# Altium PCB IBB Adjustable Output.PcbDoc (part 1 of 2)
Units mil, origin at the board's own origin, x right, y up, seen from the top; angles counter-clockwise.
Board outline 3000 x 2700 mil, 4 copper layers (Top Layer, Signal Layer 1, Signal Layer 2, Bottom Layer), stack 61.2 mil thick; 75 components, 28 nets, 136 pads, 154 vias.
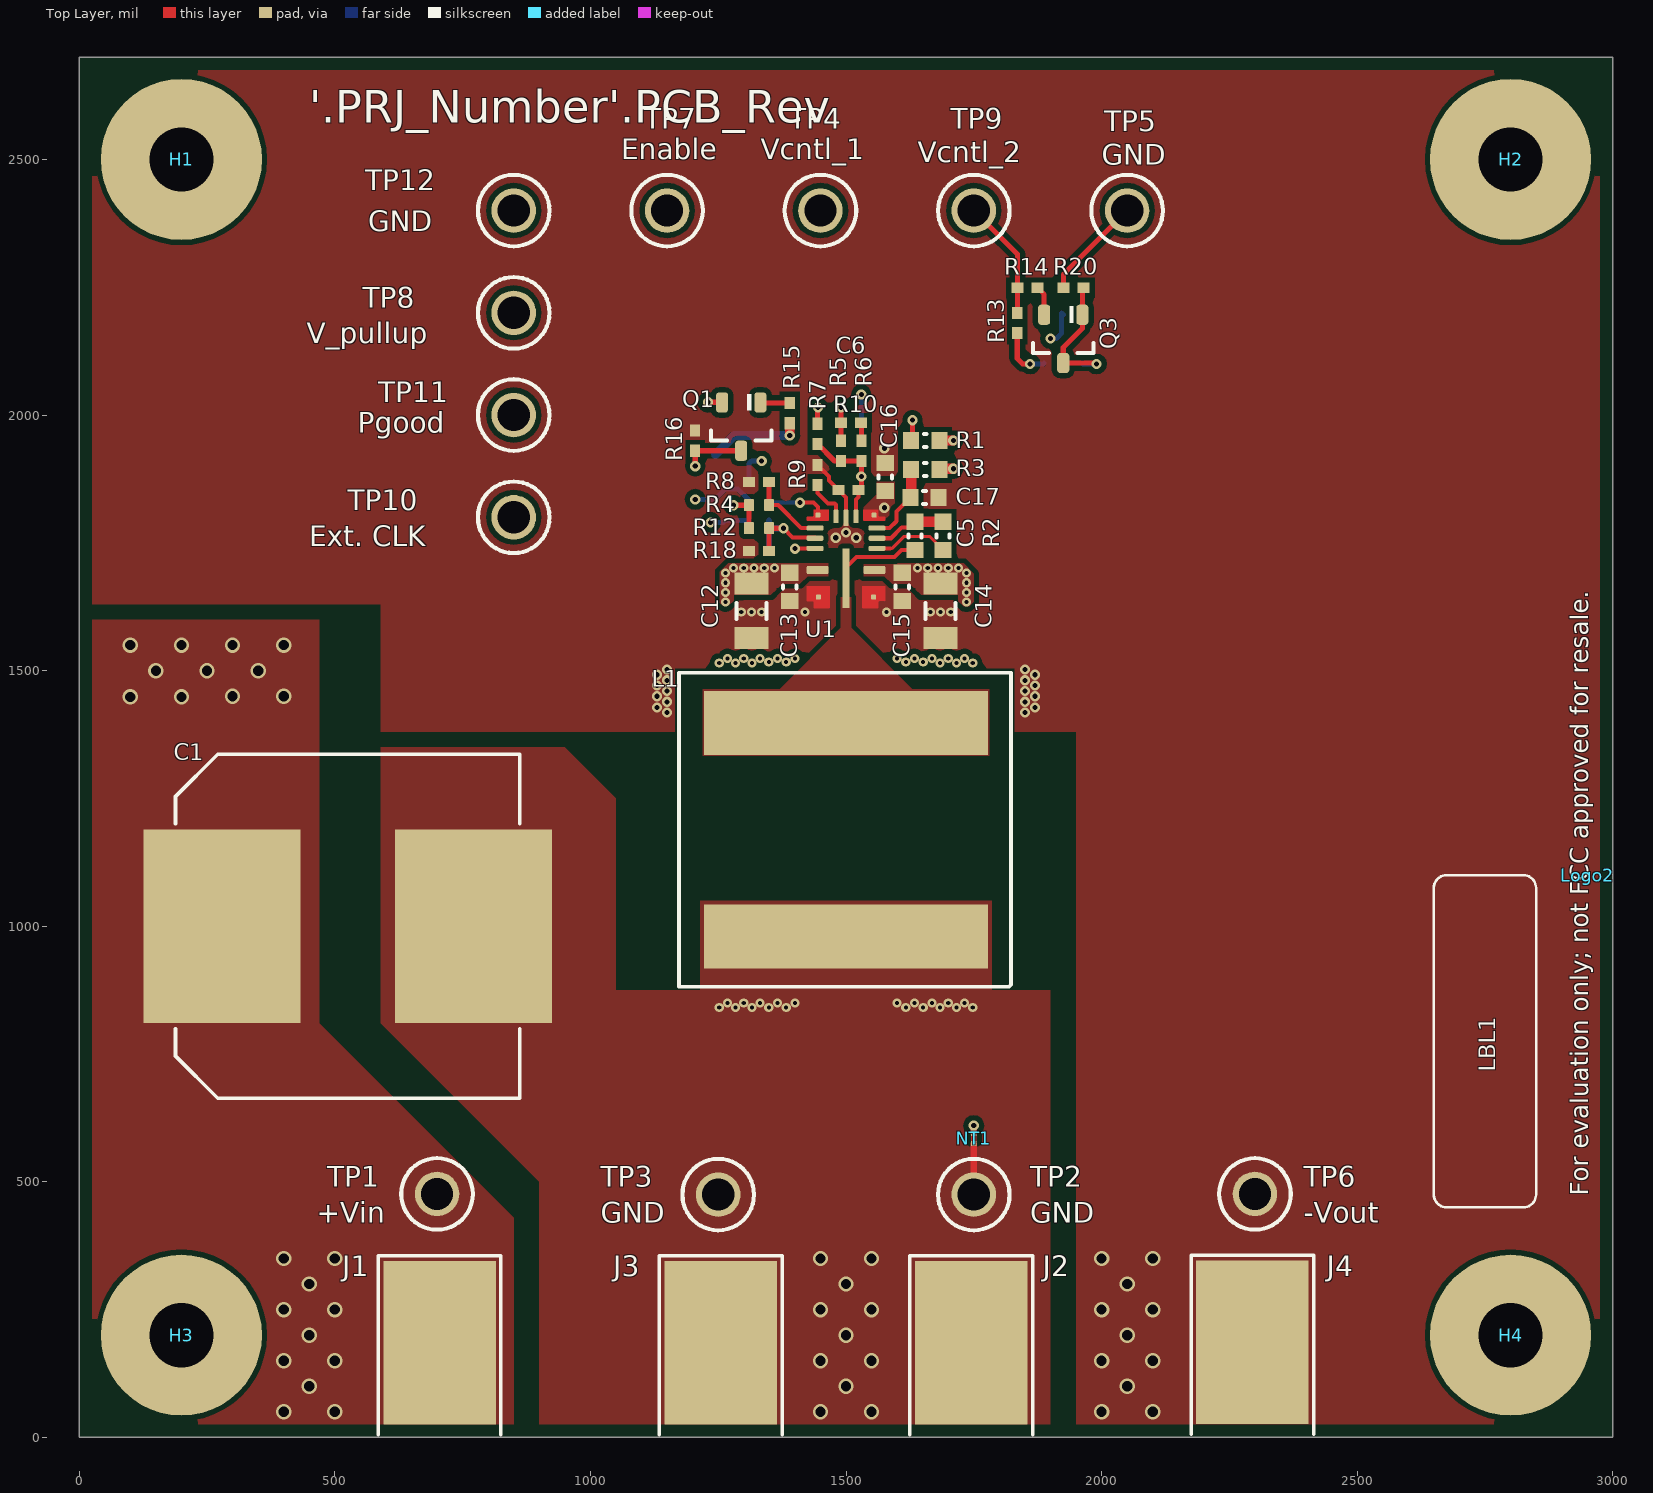
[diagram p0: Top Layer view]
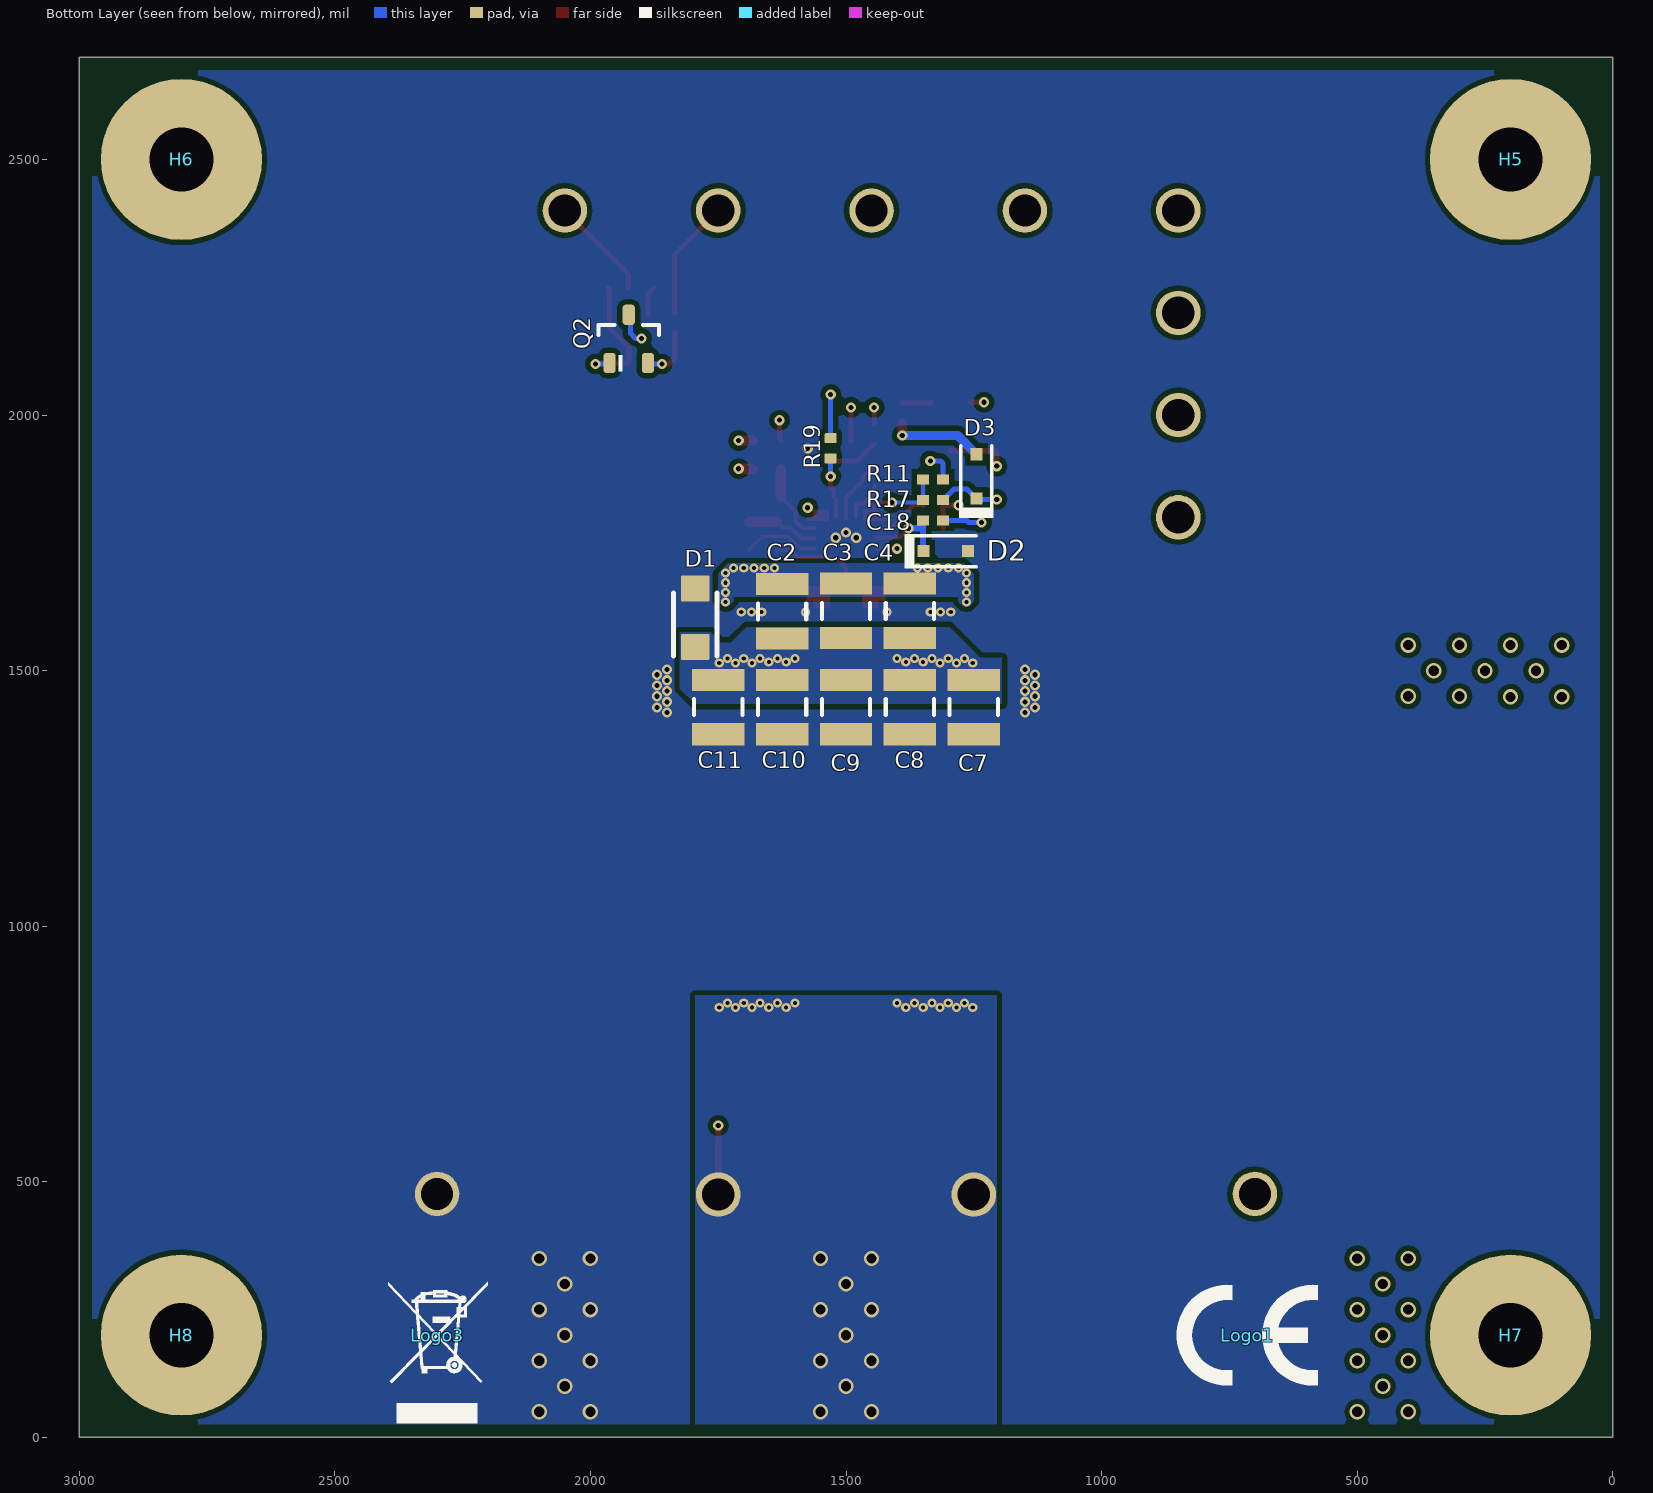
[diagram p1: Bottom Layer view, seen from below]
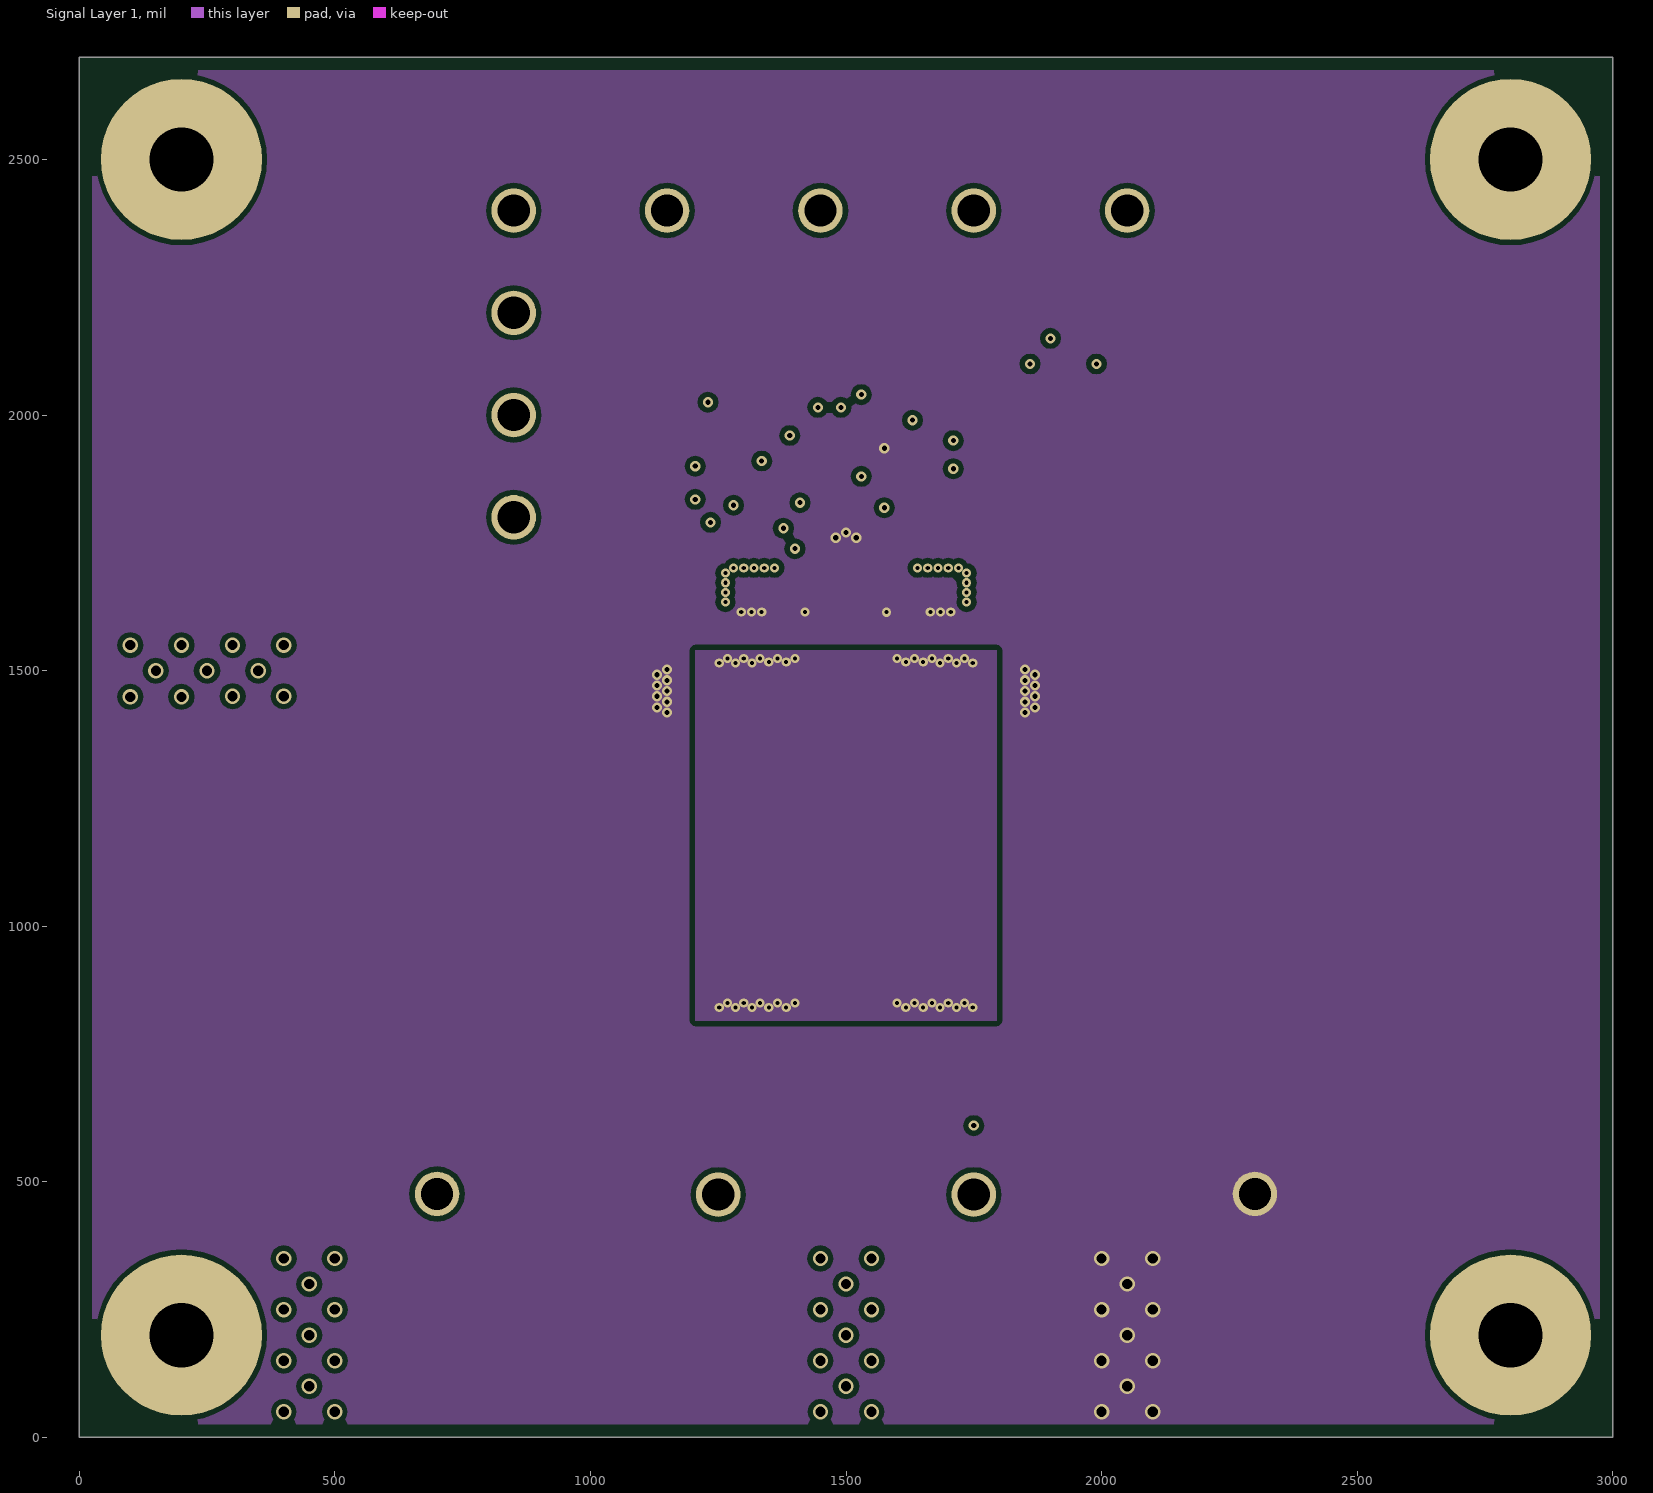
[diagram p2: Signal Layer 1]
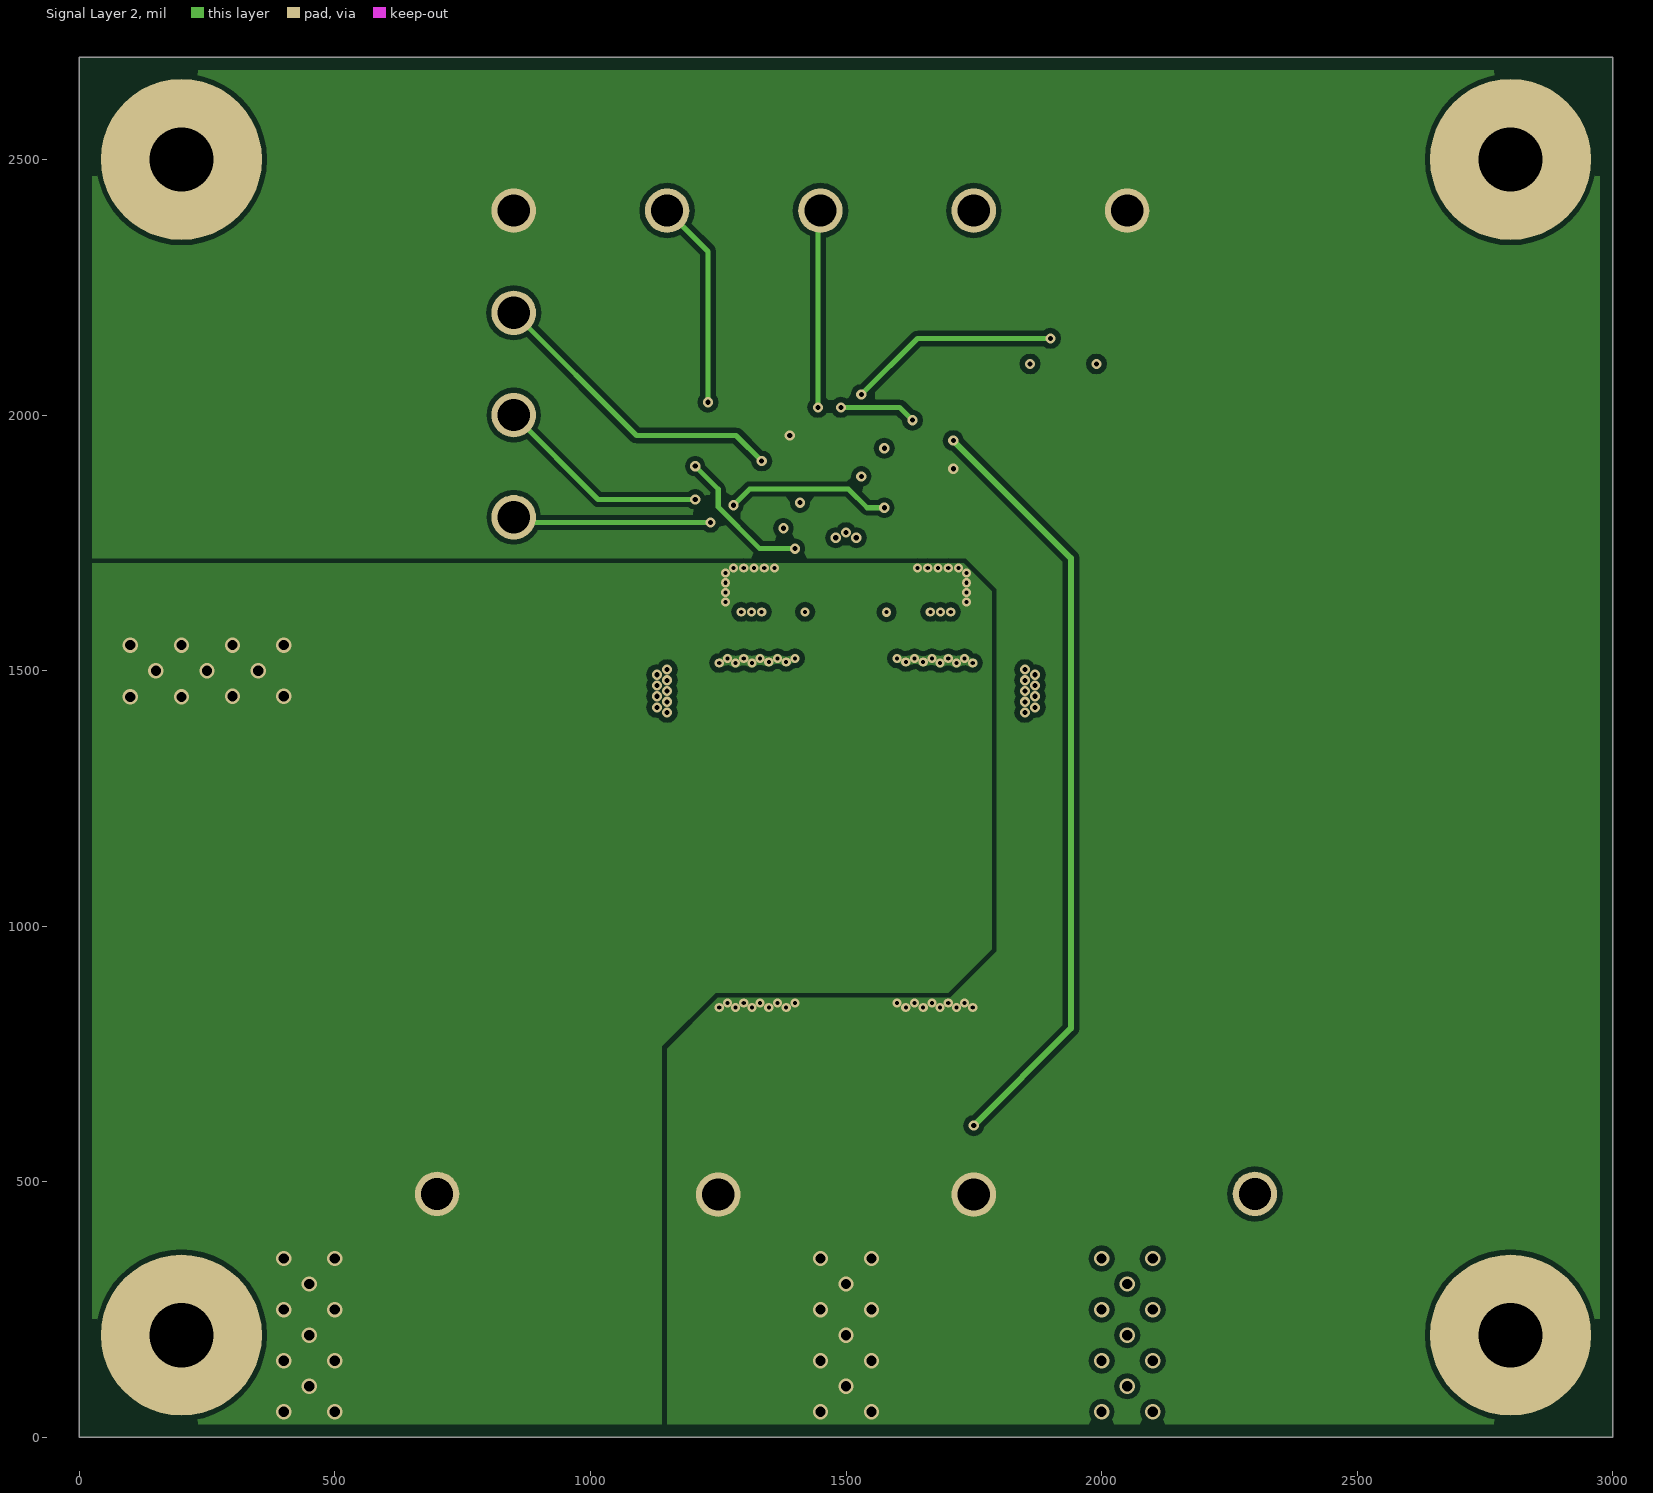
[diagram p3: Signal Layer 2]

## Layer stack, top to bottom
Top Solder: solder mask 0.4, Solder Resist, Dk 3.5
Top Layer: signal copper 1.4
Dielectric 2: prepreg 12.3, Dk 4.2
Signal Layer 1: signal copper 1.4
Dielectric 3: core 31, Dk 4.2
Signal Layer 2: signal copper 1.4
Dielectric1: prepreg 12.3, FR-4 High Tg, Dk 4.2
Bottom Layer: signal copper 1.4
Bottom Solder: solder mask 0.4, Solder Resist, Dk 3.5

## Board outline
0,0 3000,0 3000,2700 0,2700

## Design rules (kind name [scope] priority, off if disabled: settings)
AcuteAngle [All] p1: minimum=4.50000000000000E+0001 checktracksonly=FALSE
AssemblyTestPointUsage [All] p1: valid=2
BoardOutlineClearance BoardOutlineClearance_MountingHoles [OnCopper and InComponentClass('Mounting Holes')] p1: gap=40 ignorepadtopadclearanceinfootprint=FALSE
BoardOutlineClearance BoardOutlineClearance_Poly [OnCopper and IsPoly] p2: gap=25 ignorepadtopadclearanceinfootprint=FALSE
BoardOutlineClearance [OnCopper and Not InComponentClass('Logo') and not InComponentClass('FiducialMark') and not InRegion(1000,500,4000,800) and not InPoly] p3: gap=25 ignorepadtopadclearanceinfootprint=FALSE
Clearance Clearance_Keepouts [((IsTrack Or IsArc) And Not InPoly) And IsFree and IsKeepOut vs ((IsTrack Or IsArc) And Not InPoly) And IsFree and IsKeepOut] p1: gap=0 ignorepadtopadclearanceinfootprint=FALSE
Clearance Clearance_Poly [InPolygon] p2: gap=10 ignorepadtopadclearanceinfootprint=TRUE
Clearance Clearance_FiducialMark [IsKeepOut and InComponentClass('FiducialMark') vs IsPad and InComponentClass('FiducialMark')] p3: gap=0 ignorepadtopadclearanceinfootprint=FALSE
Clearance [All] p4: gap=7.87 ignorepadtopadclearanceinfootprint=TRUE
ComponentClearance ComponentClearance_MountingHoles_FiducialMarks [InComponentClass('Mounting Holes') vs InComponentClass('FiducialMark')] p1: gap=50 collisioncheckmode=3 verticalgap=10 showdistances=FALSE
ComponentClearance ComponentClearance_Shunt [InComponentClass('Header') vs InComponentClass('Shunt')] p2: gap=0 collisioncheckmode=3 verticalgap=0 showdistances=FALSE
ComponentClearance ComponentClearance_Logo [InComponentClass('Logo')] p3: gap=30 collisioncheckmode=3 verticalgap=10 showdistances=FALSE
ComponentClearance ComponentClearance_ScrewToNut [(HasFootprint('NY PMS 440 0025 PH')) vs (HasFootprint('Keystone_1902C'))] p4: gap=5 collisioncheckmode=3 verticalgap=10 showdistances=FALSE
ComponentClearance ComponentClearance_MountingHoles [InComponentClass('Mounting Holes')] p5: gap=100 collisioncheckmode=3 verticalgap=100000 showdistances=FALSE
ComponentClearance ComponentClearance_SmallPassives [HasFootprint('0201*') or HasFootprint('0402*') or HasFootprint('0508') or HasFootprint('0603*') or HasFootprint('0612') or HasFootprint('0805*') or HasFootprint('0815*') or HasFootprint('0830*') or HasFootprint('1206*') or HasFootprint('1210*') or HasFootprint('1808*') or HasFootprint('1812*') or HasFootprint('1825*') or HasFootprint('2010*') or HasFootprint('2220*') or HasFootprint('2225*') or HasFootprint('2512*') or HasFootprint('2728*') or HasFootprint('3518*') vs HasFootprint('0201*') or HasFootprint('0402*') or HasFootprint('0508') or HasFootprint('0603*') or HasFootprint('0612') or HasFootprint('0805*') or HasFootprint('0815*') or HasFootprint('0830*') or HasFootprint('1206*') or HasFootprint('1210*') or HasFootprint('1808*') or HasFootprint('1812*') or HasFootprint('1825*') or HasFootprint('2010*') or HasFootprint('2220*') or HasFootprint('2225*') or HasFootprint('2512*') or HasFootprint('2728*') or HasFootprint('3518*')] p6: gap=14.96 collisioncheckmode=3 verticalgap=10 showdistances=FALSE
ComponentClearance ComponentClearance_THtoSMT [IsThruComponent vs IsSMTComponent] p7: gap=30 collisioncheckmode=3 verticalgap=30 showdistances=FALSE
ComponentClearance ComponentClearance_THtoTH [IsThruComponent vs IsThruComponent] p8: gap=20 collisioncheckmode=3 verticalgap=30 showdistances=FALSE
ComponentClearance [All] p9: gap=20 collisioncheckmode=3 verticalgap=10 showdistances=FALSE
DiffPairsRouting [All] p1: maxlimit=100 minlimit=10 mostfreqgap=10 toplayer_minwidth=15 toplayer_maxwidth=15 toplayer_prefwidth=15 midlayer1_minwidth=15 midlayer1_maxwidth=15 midlayer1_prefwidth=15 midlayer2_minwidth=15 midlayer2_maxwidth=15 midlayer2_prefwidth=15 bottomlayer_minwidth=15 bottomlayer_maxwidth=15 bottomlayer_prefwidth=15 maxuncoupledlength=1000
FabricationTestPointUsage TestPointUsage [All] p1: valid=2 allowmultiple=FALSE
FabricationTestpoint Testpoint [All] p1: side=3 testpointundercomponent=TRUE minsize=40 maxsize=100 preferedsize=60 minholesize=0 maxholesize=40 preferedholesize=32 testpointgrid=1 allowsidetop=TRUE allowsidebottom=TRUE usegrid=TRUE gridtolerance=0.01
FanoutControl Fanout_LCC [IsLCC] p1: bgadir=Out bgaviamode=Centered fanoutstyle=Auto fanoutdirection=Alternating viagrid=1 // Fanout_LCC (Default Rule)
FanoutControl Fanout_BGA [IsBGA] p2: bgadir=Out bgaviamode=Centered fanoutstyle=Auto fanoutdirection=Alternating viagrid=1 // Fanout_BGA (Default Rule)
FanoutControl Fanout_Default [All] p4: bgadir=Out bgaviamode=Centered fanoutstyle=Auto fanoutdirection=Alternating viagrid=1 // Fanout_Default (Default Rule)
FanoutControl Fanout_Small [(CompPinCount < 5)] p5: bgadir=Out bgaviamode=Centered fanoutstyle=Auto fanoutdirection=OutThenIn viagrid=1 // Fanout_Small (Default Rule)
HoleSize [All] p1: absolutevalues=TRUE maxlimit=251 minlimit=8 maxpercent=80.000 minpercent=20.000
MinimumAnnularRing MinimumAnnularRing_ThermalPadVias [IsVia and InAnyComponent] p1: minimumring=5
MinimumAnnularRing [All] p2: minimumring=5
MinimumSolderMaskSliver MinimumSolderMaskSliver_Logo [InComponentClass('Logo') vs InComponentClass('Logo')] p1: minsoldermaskwidth=0.7
MinimumSolderMaskSliver [All] p2: minsoldermaskwidth=3.94
PlaneConnect [All] p1: planeconnectstyle=Direct reliefexpansion=10 reliefentries=4 reliefconductorwidth=10 reliefairgap=10
PolygonConnect [All] p1: connectstyle=Direct reliefconductorwidth=10 reliefentries=4 polygonreliefangle="90 Angle" airgapwidth=10
RoutingVias ThermalPadVias [IsVia and InAnyComponent] p1: holewidth=7.87 width=19.68 viastyle="Through Hole" minholewidth=7.87 minwidth=18 maxholewidth=12.99 maxwidth=30
RoutingVias [All] p2: holewidth=16 width=34 viastyle="Through Hole" minholewidth=7.87 minwidth=18 maxholewidth=40 maxwidth=65
SilkToBoardRegionClearance [Not ((IsComment or IsDesignator) And (Hide <> 'False')) and not InRegion(1000,500,4000,800)] p1:
SilkToSilkClearance SilkToSilkClearance_Pb-FreeLogo [(HasFootprint('Pb-Free_Overlay_Medium') OR HasFootprint('Pb-Free_Overlay_Small')) vs (HasFootprint('Pb-Free_Overlay_Medium') OR HasFootprint('Pb-Free_Overlay_Small'))] p1: silktosilkclearance=0
SilkToSilkClearance [All] p2: silktosilkclearance=3.94
SilkToSolderMaskClearance SilkToComponentPadClearance [(IsPad or IsFill or IsRegion) and InAnycomponent] p1: minsilkscreentomaskgap=5 clearancetoexposedcopper=TRUE
SilkToSolderMaskClearance "Silk to Solder Mask Opening" [All] p2: minsilkscreentomaskgap=3.94 clearancetoexposedcopper=FALSE
SolderMaskExpansion [All] p1: expansion=1.97
UnRoutedNet [All] p1: checkbadconnections=TRUE
Width [All] p1: maxlimit=100 minlimit=6 preferedwidth=10 checkconnectedcopper=TRUE
14 further rules are at their usual default settings.

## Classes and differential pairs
component class "IBB Adjustable Output_BlankSheet": C1 C2 C3 C4 C5 C6 C7 C8 C9 C10 C11 C12 C13 C14 C15 C16 C17 C18 D1 D2 D3 J1 J2 J3 J4 L1 NT1 Q1 Q2 Q3 R1 R2 R3 R4 R5 R6 R7 R8 R9 R10 R11 R12 R13 R14 R15 R16 R17 R18 R19 R20 TP1 TP2 TP3 TP4 TP5 TP6 TP7 TP8 TP9 TP10 TP11 TP12 U1
component class Label: LBL1
component class "IBB Adjustable Output_Hardware": H1 H2 H3 H4 H5 H6 H7 H8 LBL1 Logo1 Logo2 Logo3
component class "Mounting Holes": H1 H2 H3 H4

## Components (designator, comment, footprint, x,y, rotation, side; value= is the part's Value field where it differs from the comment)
C1 "EMXB250ARA102MLH0S" CAPSMT_62_LH0 525,1000 r0 top value=1000uF
C2 "GCM32ER71E106KA57K" 1210_270L 1625,1616 r270 bottom value=10uF
C3 "GCM32ER71E106KA57K" 1210_270L 1500,1617 r270 bottom value=10uF
C4 "GCM32ER71E106KA57K" 1210_270L 1375,1617 r270 bottom value=10uF
C5 "CGA3E2X7R1E104K080AA" 0603L 1635,1763.66 r90 top value=0.1uF
C6 "" 0402L 1510,1985 r0 top value=10pF
C7 "CL32B226KOJVPNE" 1210_270L 1250,1428.66 r270 bottom value=22uF
C8 "CL32B226KOJVPNE" 1210_270L 1375,1428.66 r270 bottom value=22uF
C9 "CL32B226KOJVPNE" 1210_270L 1500,1428.66 r270 bottom value=22uF
C10 "CL32B226KOJVPNE" 1210_270L 1625,1428.66 r270 bottom value=22uF
C11 "CL32B226KOJVPNE" 1210_270L 1750,1428.66 r270 bottom value=22uF
C12 "CL31B225KBHVPNE" C1206 1315,1617 r270 top value=2.2uF
C13 "CGA3E3X7R1H224K080AB" 0603L 1390,1664 r270 top value=0.22uF
C14 "CL31B225KBHVPNE" C1206 1685,1617 r270 top value=2.2uF
C15 "CGA3E3X7R1H224K080AB" 0603L 1610,1664 r270 top value=0.22uF
C16 "CGA3E1X7R1C105K080AC" 0603L 1576.77,1878.66 r90 top value=1uF
C17 "GCM188R71E224KA55D" 0603L 1653.78,1838.66 r0 top value=0.22uF
C18 "DNP" 0402L 1330,1793.66 r0 bottom value=100pF
D1 "V3FL45HM3/H" DO-219AB 1795,1603.66 r90 bottom value=45V
D2 "RB510VM-30FHTE-17" SOD-323 1305,1733.66 r180 bottom value=30V
D3 "RB510VM-30FHTE-17" SOD-323 1245,1880 r90 bottom value=30V
H1 "NY PMS 440 0025 PH" "NY PMS 440 0025 PH" 200,2500 r0 top locked
H2 "NY PMS 440 0025 PH" "NY PMS 440 0025 PH" 2800,2500 r0 top locked
H3 "NY PMS 440 0025 PH" "NY PMS 440 0025 PH" 200,200 r0 top locked
H4 "NY PMS 440 0025 PH" "NY PMS 440 0025 PH" 2800,200 r0 top locked
H5 "1902C" Keystone_1902C 200,2500 r180 bottom locked
H6 "1902C" Keystone_1902C 2800,2500 r180 bottom locked
H7 "1902C" Keystone_1902C 200,200 r180 bottom locked
H8 "1902C" Keystone_1902C 2800,200 r180 bottom locked
J1 "+Vin" 6091 705,0 r90 top
J2 "GND" 6092 1745,0 r90 top
J3 "GND" 6092 1255,0 r90 top
J4 "-Vout" CONN_108-0907-001 2295,1.34 r90 top
L1 "XAL1510-472MEB" XAL1510 1500,1188.66 r270 top value=4.7uH
LBL1 "THT-14-423-10" Label_650x200 2750,775 r90 top
Logo1 "CE Mark" CE_Mark_5mm 715,200 r180 bottom
Logo2 "FCC disclaimer" FCC_disclaimer 2950,1100 r90 top
Logo3 "WEEE logo" WEEE_Minimum 2300,200 r180 bottom
NT1 "Net-Tie" Net-Tie_10mil 1750,585 r270 top net-tie
Q1 "PMBT3906,235" SOT-23 1295,1977.44 r270 top value=40V
Q2 "" SOT-23 1925,2149.02 r90 bottom value=40V
Q3 "" SOT-23 1925,2149.02 r270 top value=40V
R1 "CRCW060349R9FKEA" 0603L 1655,1950 r0 top value=49.9
R2 "RMCF0603ZT0R00" 0603L 1690,1763.66 r90 top value=0
R3 "RMCF0603ZT0R00" 0603L 1655,1893.66 r0 top value=0
R4 "RMCF0402ZT0R00" "FP-RMCF0402ZT0R00_0402 (1005 metric)-0" 1330,1823.66 r0 top value=0
R5 "CRCW0402110KFKED" 0402L 1490,1930 r90 top value=110k
R6 "CRCW04024K99FKED" 0402L 1530,1930 r90 top value=4.99k
R7 "CRCW040212K1FKED" 0402L 1444.19,1963.35 r90 top value=12.1k
R8 "DNP" 0402L 1330,1868.66 r0 top value=20.0k
R9 "CRCW040240K2FKED" 0402L 1444.19,1882.6 r270 top value=40.2k
R10 "CRCW04021K00FKED" 0402L 1505,1853.66 r0 top value=1.00k
R11 "RMCF0402FT100K" 0402L 1330,1873.66 r180 bottom value=100k
R12 "RMCF0402ZT0R00" "FP-RMCF0402ZT0R00_0402 (1005 metric)-0" 1330,1778.66 r180 top value=0
R13 "" 0402L 1835,2180 r90 top value=1.00k
R14 "" 0402L 1855,2249.02 r180 top value=1.00k
R15 "CRCW040210K0FKED" 0402L 1390,2003.66 r90 top value=10.0k
R16 "RMCF0402FT100K" 0402L 1205,1949.88 r270 top value=100k
R17 "RMCF0402FT100K" 0402L 1330,1833.66 r0 bottom value=100k
R18 "DNP" 0402L 1330,1733.66 r0 top value=10.0k
R19 "DNP" "FP-RMCF0402ZT0R00_0402 (1005 metric)-0" 1530,1935 r90 bottom value=0
R20 "DNP" 0402L 1945,2249.02 r0 top value=9.76k
TP1 "+Vin" Keystone5010 700,476.34 r0 top
TP2 "GND" Keystone5011 1750,475 r0 top
TP3 "GND" Keystone5011 1250,475 r0 top
TP4 "Vcntl_1" Keystone5012 1450,2400 r0 top
TP5 "GND" Keystone5011 2050,2400 r0 top
TP6 "-Vout" Keystone5014 2300,476.34 r0 top
TP7 "Enable" Keystone5012 1150,2400 r0 top
TP8 "V_pullup" Keystone5012 850,2200 r0 top
TP9 "Vcntl_2" Keystone5012 1750,2400 r0 top
TP10 "Ext. CLK" Keystone5012 850,1800 r0 top
TP11 "Pgood" Keystone5012 850,2000 r0 top
TP12 "GND" Keystone5011 850,2400 r0 top
U1 "LM61495QRPHRQ1" RPH0016A 1500,1718.66 r180 top

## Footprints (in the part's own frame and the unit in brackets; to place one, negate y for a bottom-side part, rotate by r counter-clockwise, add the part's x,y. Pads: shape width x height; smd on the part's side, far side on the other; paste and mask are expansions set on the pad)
0402L [mm] "0402 from SM-752 data"
  rect 0.6x0.5 smd: 1(-0.5,0) 2(0.5,0)
  body extent -0.55,-0.3 0.55,0.3, height 0.6
0603L [mm] "0603 from SM-752 data"
  rect 0.8x0.85 smd: 1(-0.7,0) 2(0.7,0)
  silkscreen extent -0.07,-0.33 0.07,0.33, body extent -0.87,-0.47 0.87,0.47, height 1
1210_270L [mm] "1210"
  rect 1.1x2.6 smd: 1(-1.35,0) 2(1.35,0)
  silkscreen extent -0.4,-1.2 0.4,1.2, body extent -1.7,-1.35 1.7,1.35, height 2.7
6091 [mil] "Keystone Insulated End Launch Banana Jack"
  rect 320x220 smd: 1(185,0)
  silkscreen extent 5,-120 355,120, body extent -666,-216 271,216, height 227
6092 [mil] "Keystone Insulated End Launch Banana Jack"
  rect 320x220 smd: 1(185,0)
  silkscreen extent 5,-120 355,120, body extent -666,-216 271,216, height 227
C1206 [mm] "Chip Capacitor, Body 3.2x1.6mm, IPC High Density"
  rect 1.1x1.7 smd: 1(-1.35,0) 2(1.35,0)
  silkscreen extent -0.4,-0.75 0.4,0.75, body extent -1.7,-0.9 1.7,0.9, height 1.3
CAPSMT_62_LH0 [mm] "16 x 16.5mm:  Chemi-Con LH0"
  rect 7.8x9.6 smd: 1(-6.25,0) 2(6.25,0)
  silkscreen extent -8.55,-8.55 8.55,8.55, body extent -8.55,-8.55 8.55,8.55, height 17
CE_Mark_5mm [mil] "Minimum text height for CE Mark"
  silkscreen extent -138,-98 138,98
CONN_108-0907-001 [mil] "Keystone Insulated End Launch Banana Jack"
  rect 320x220 smd: 1(185,0)
  silkscreen extent 5,-120 355,120, body extent -666,-216 271,216, height 227
DO-219AB [mm] "Vishay Semiconductor"
  rrect8% 1.3x1.4 smd: 1(-1.45,0) 2(1.45,0)
  silkscreen extent -1.9,-1.07 1.23,1.07, body extent -1.95,-0.95 1.95,0.95, height 1.09
FCC_disclaimer [mil]
"FP-RMCF0402ZT0R00_0402 (1005 metric)-0" [mm]
  rrect20% 0.5x0.6 smd paste+0 mask+0: 1(-0.5,0) 2(0.5,0)
  body extent -0.85,-0.4 0.85,0.4, height 0.25
Keystone5010 [mil] "Keystone Multipurpose loops"
  round 87 hole 63: 1(0,0)
  silkscreen extent -70,-70 70,70, body extent -63,-63 63,62, height 319
Keystone5011 [mil] "Keystone Multipurpose loops"
  round 87 hole 63: 1(0,0)
  silkscreen extent -70,-70 70,70, body extent -63,-63 63,62, height 319
Keystone5012 [mil] "Keystone Multipurpose loops"
  round 87 hole 63: 1(0,0)
  silkscreen extent -70,-70 70,70, body extent -63,-63 63,62, height 319
Keystone5014 [mil] "Keystone Multipurpose loops"
  round 87 hole 63: 1(0,0)
  silkscreen extent -70,-70 70,70, body extent -63,-63 63,62, height 319
Keystone_1902C [mil] "Hex Standoff, 4-40 threaded, nylon"
  round 1 on Mech4: 0(0,0)
  body extent -145,-126 146,126, height 501
Label_650x200 [mil] "Thermal Transfer Label"
  round 1 on Mech13: 0(0,0)
  silkscreen extent -325,-100 325,100, body extent -325,-100 325,100, height 1
Net-Tie_10mil [mil] "10mil net tie, no solder mask opening, no solder paste"
  rect 10x10 smd paste-5 mask-5: 1(-10,0) 2(10,0)
  Top Layer region: -6,5 6,5 6,-5 -6,-5
"NY PMS 440 0025 PH" [mm] "4-40 nylon screw and mounting hole"
  round 8 hole 3.2: 1(0,0)
  body extent -3.3,-3.3 3.3,3.3, height 2.69
RPH0016A [mm] "QFN, 16-Leads, Body 3.5x4.5mm"
  rrect40% 0.25x0.25 smd paste-0.25: 1(-1.375,1.9) 6(-1.4,-2.175) 10(1.4,-2.175) 15(1.375,1.9)
  rrect25% 1.075x0.4 smd: 2(-1.413,0.55) 14(1.413,0.55)
  rrect40% 0.825x0.25 smd: 3(-1.538,-0.525) 4(-1.538,-1.025) 5(-1.538,-1.525) 11(1.538,-1.525) 12(1.538,-1.025) 13(1.538,-0.525)
  rrect40% 0.25x0.675 smd: 7(-0.5,-2.113) 9(0.5,-2.113)
  rrect40% 0.25x0.825 smd: 8(0,-2.038)
  rrect29% 0.35x2.975 smd: 16(0,0.963)
  Top Layer region: 1.95,-2.05 1.946,-2.069 1.935,-2.085 1.919,-2.096 1.9,-2.1 1.9,-2.1 1.65,-2.1 1.631,-2.104 1.615,-2.115 1.604,-2.131 1.6,-2.15 1.6,-2.15 1.6,-2.4 1.596,-2.419 1.585,-2.435 1.569,-2.446 1.55,-2.45 1.55,-2.45 0.9,-2.45 0.881,-2.446 0.865,-2.435 0.854,-2.419 0.85,-2.4 0.85,-2.4 0.85,-1.95 0.854,-1.931 0.865,-1.915 0.881,-1.904 0.9,-1.9 0.9,-1.9 1.9,-1.9 1.919,-1.904 1.935,-1.915 1.946,-1.931 1.95,-1.95 1.95,-1.95
  Top Layer region: -1.95,-2.05 -1.946,-2.069 -1.935,-2.085 -1.919,-2.096 -1.9,-2.1 -1.9,-2.1 -1.65,-2.1 -1.631,-2.104 -1.615,-2.115 -1.604,-2.131 -1.6,-2.15 -1.6,-2.15 -1.6,-2.4 -1.596,-2.419 -1.585,-2.435 -1.569,-2.446 -1.55,-2.45 -1.55,-2.45 -0.9,-2.45 -0.881,-2.446 -0.865,-2.435 -0.854,-2.419 -0.85,-2.4 -0.85,-2.4 -0.85,-1.95 -0.854,-1.931 -0.865,-1.915 -0.881,-1.904 -0.9,-1.9 -0.9,-1.9 -1.9,-1.9 -1.919,-1.904 -1.935,-1.915 -1.946,-1.931 -1.95,-1.95 -1.95,-1.95
  Top Layer region: -1.95,1.4 -1.95,2.05 -1.946,2.069 -1.935,2.085 -1.919,2.096 -1.9,2.1 -1.9,2.1 -1.65,2.1 -1.631,2.104 -1.615,2.115 -1.604,2.131 -1.6,2.15 -1.6,2.15 -1.6,2.4 -1.596,2.419 -1.585,2.435 -1.569,2.446 -1.55,2.45 -1.55,2.45 -0.85,2.45 -0.831,2.446 -0.815,2.435 -0.804,2.419 -0.8,2.4 -0.8,2.4 -0.8,1.4 -0.804,1.381 -0.815,1.365 -0.831,1.354 -0.85,1.35 -0.85,1.35 -1.9,1.35 -1.919,1.354 -1.935,1.365 -1.946,1.381 -1.95,1.4
  Top Layer region: 1.95,1.4 1.95,2.05 1.946,2.069 1.935,2.085 1.919,2.096 1.9,2.1 1.9,2.1 1.65,2.1 1.631,2.104 1.615,2.115 1.604,2.131 1.6,2.15 1.6,2.15 1.6,2.4 1.596,2.419 1.585,2.435 1.569,2.446 1.55,2.45 1.55,2.45 0.85,2.45 0.831,2.446 0.815,2.435 0.804,2.419 0.8,2.4 0.8,2.4 0.8,1.4 0.804,1.381 0.815,1.365 0.831,1.354 0.85,1.35 0.85,1.35 1.9,1.35 1.919,1.354 1.935,1.365 1.946,1.381 1.95,1.4
  body extent -1.8,-2.3 1.8,2.3, height 1
SOD-323 [mm] "NXP recommended land pattern"
  rect 0.6x0.6 smd paste-0.05: 1(-1.1,0) 2(1.1,0)
  silkscreen extent -2.06,-0.86 1.53,0.86, body extent -1.3,-0.67 1.3,0.68, height 1.1
SOT-23 [mm] "SOT23, 3-Leads, Body 2.9x1.3mm, Pitch 0.95mm, Lead Span 2.5mm, IPC Medium Density"
  rrect50% 1x0.6 smd: 1(-1.2,0.95) 2(-1.2,-0.95) 3(1.2,0)
  silkscreen extent -1.63,-1.5 0.7,1.5, body extent -1.16,-1.45 1.21,1.45, height 1
WEEE_Minimum [mil] "WEEElie bin"
  silkscreen extent -95,-172 99,104
XAL1510 [mm] "COILCRAFT"
  rect 3.18x14.1 smd: 1(-5.3,0) 2(5.3,0)
  silkscreen extent -7.8,-8.3 7.8,8.2, body extent -7.7,-8.2 7.7,8.2, height 11

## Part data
C1: library part Capacitor_Polarized, "CAP, Al Electrolytic, 1000uF, 25V, +/-20%, 0.1ohm ESR @ 100kHz, 1.12Arms @ 100kHz, SMT", Alternate Manufacturer=-, Manufacturer="United Chemi-Con", Value1=25V
C2 C3 C4: library part Capacitor, "CAP, CERM, 10uF, 25V, X7R, 10%, 1210", Alternate Manufacturer=-, Manufacturer=Murata, Value1=25V
C5: library part Capacitor, "CAP, CERM, 0.1uF, 25V, X7R, 10%, 0603", Alternate Manufacturer=-, Manufacturer=TDK, Value1=25V
C6: library part CMP-0006307-2, "CAP, CERM, 10 pF, 50 V, +/- 5%, C0G/NP0, AEC-Q200 Grade 1, 0402", Cap_Case=0402, Manufacturer=TDK, PartNumber=CGA2B2C0G1H100D050BA, Supplier Part Number 1=445-5584-1-ND, TempCo=C0G/NP0, Tolerance_%=5%, Value1=Unknown, Value2=50V, ValueDisplayed=10pF
C7 C8 C9 C10 C11: library part CMP-0083755-1, "CAP, CERM, 22 µF, 16 V,+/- 10%, X7R, AEC-Q200 Grade 1, 1210", Cap_Case=1210, Manufacturer="Samsung Electro-Mechanics", TempCo=X7R, Tolerance_%=10%, Value2=16V, ValueDisplayed=22µF
C12 C14: library part Capacitor, "CAP, CERM, 2.2uF, 50V, X7R, 10%, 1206", Alternate Manufacturer=-, Manufacturer=Samsung, Value1=50V
C13 C15: library part CMP-0007094-5, "CAP, CERM, 0.22 uF, 50 V, +/- 10%, X7R, AEC-Q200 Grade 1, 0603", Cap_Case=0603, Manufacturer=TDK, Supplier Part Number 1=445-6926-1-ND, TempCo=X7R, Tolerance_%=10%, Value1="0.021699 ohm", Value2=50V, ValueDisplayed=0.22uF
C16: library part CMP-0079607-1, "CAP, CERM, 1 µF, 16 V,+/- 10%, X7R, AEC-Q200 Grade 1, 0603", Cap_Case=0603, Manufacturer=TDK, Supplier Part Number 1=445-12539-1-ND, TempCo=X7R, Tolerance_%=10%, Value2=16V, ValueDisplayed=1µF
C17: library part CMP-0007140-4, "CAP, CERM, 0.22 uF, 25 V, +/- 10%, X7R, AEC-Q200 Grade 1, 0603", Cap_Case=0603, Manufacturer=MuRata, Supplier Part Number 1=490-4935-1-ND, TempCo=X7R, Tolerance_%=10%, Value1=Unknown, Value2=25V, ValueDisplayed=0.22uF
C18: library part CMP-0006308-2, "CAP, CERM, 100 pF, 50 V, +/- 5%, C0G/NP0, AEC-Q200 Grade 1, 0402", Cap_Case=0402, Manufacturer=TDK, PartNumber=CGA2B2C0G1H101J050BA, Supplier Part Number 1=445-5596-1-ND, TempCo=C0G/NP0, Tolerance_%=5%, Value1=Unknown, Value2=50V, ValueDisplayed=100pF
D1: library part Diode_Schottky, "Diode, Schottky, 45V, 3A, DO-219AB (SMF)", Alternate Manufacturer=-, Manufacturer=Vishay, Value1=3A
D2 D3: library part Diode_Schottky, "Diode, Schottky, 30V, 100mA, SOD-323F", Alternate Manufacturer=-, Manufacturer=Rohm
H1 H2 H3 H4: library part CMP-0003617-1, "Machine Screw, Round, #4-40 x 1/4, Nylon, Philips panhead", Manufacturer="B&F Fastener Supply", Supplier Part Number 1=H542-ND
H5 H6 H7 H8: library part CMP-0003610-1, "Standoff, Hex, 0.5\"L #4-40 Nylon", Manufacturer=Keystone, Supplier Part Number 1=36-1902C-ND
J1: library part CMP-0055167-2, "Standard Banana Jack, Insulated, Red", Manufacturer=Keystone, PartNumber=6091, Supplier Part Number 1=36-6091-ND
J2 J3: library part CMP-0055168-2, "Standard Banana Jack, Insulated, Black", Manufacturer=Keystone, PartNumber=6092, Supplier Part Number 1=36-6092-ND
J4: library part CMP-0055400-2, "BANANA JACK, 15A, Insulated, Nylon,Yellow", Manufacturer="Cinch Connectivity", PartNumber=108-0907-001, Supplier Part Number 1=J154-ND
L1: library part CMP-0060970-1, "Inductor, Shielded, Composite, 4.7 uH, 29 A, 0.00335 ohm, SMD", Manufacturer=Coilcraft, Value1="0.00335 ohm", Value2=29A, ValueDisplayed=4.7uH
LBL1: library part CMP-0003625-1, "Thermal Transfer Printable Labels, 0.650\" W x 0.200\" H - 10,000 per roll", Manufacturer=Brady, Supplier Part Number 1=97C5133
Logo1: library part CMP-0074844-1
Logo2: library part CMP-0074847-1, "FCC_disclaimer"
Logo3: library part CMP-0074769-1
NT1: "Single point connection between nets."
Q1: library part BJT_PNP_C3B1E2, "Transistor, NPN, 40V, 200mA, SOT-23-3", Alternate Manufacturer=-, Manufacturer=Nexperia
Q2 Q3: library part BJT_PNP_C3B1E2, "Transistor, NPN, 40V, 200mA, SOT-23-3", Alternate Manufacturer=-, Manufacturer=Nexperia, PartNumber=PMBT3906,235
R1: library part CMP-0022448-4, "RES, 49.9, 1%, 0.1 W, AEC-Q200 Grade 0, 0603", Manufacturer=Vishay-Dale, Power_W=100mW, Supplier Part Number 1=541-49.9HCT-ND, TempCo="100 ppm/C", Tolerance_%=1%, Value2=0.1W, Value_Code=49R9, ValueDisplayed=49.9
R2 R3: library part CMP-0023343-3, "RES, 0, 1%, 0.1 W, AEC-Q200 Grade 0, 0603", Manufacturer="Stackpole Electronics Inc", Power_W=100mW, Supplier Part Number 1=RMCF0603ZT0R00CT-ND, TempCo=ppm/C, Tolerance_%=1%, Value2=0.1W, Value_Code=0
R4 R12: library part CMP-0086542-2, "RMCF/RMCP Series General Purpose Thick Film Standard Power and High Power Chip Resistor", Manufacturer=Stackpole, TempCo=-
R5: library part CMP-0025967-3, "RES, 110 k, 1%, 0.063 W, AEC-Q200 Grade 0, 0402", Manufacturer=Vishay-Dale, Power_W=63mW, Supplier Part Number 1=541-110KLCT-ND, TempCo="100 ppm/C", Tolerance_%=1%, Value2=0.063W, Value_Code=110k
R6: library part CMP-0026414-2, "RES, 4.99 k, 1%, 0.063 W, AEC-Q200 Grade 0, 0402", Manufacturer=Vishay-Dale, Power_W=63mW, Supplier Part Number 1=541-4.99KLCT-ND, TempCo="100 ppm/C", Tolerance_%=1%, Value2=0.063W, Value_Code=4k99, ValueDisplayed=4.99k
R7: library part CMP-0025991-3, "RES, 12.1 k, 1%, 0.063 W, AEC-Q200 Grade 0, 0402", Manufacturer=Vishay-Dale, Power_W=63mW, Supplier Part Number 1=541-12.1KLCT-ND, TempCo="100 ppm/C", Tolerance_%=1%, Value2=0.063W, Value_Code=12k1, ValueDisplayed=12.1k
R8: library part CMP-0026162-2, "RES, 20.0 k, 1%, 0.063 W, AEC-Q200 Grade 0, 0402", Manufacturer=Vishay-Dale, PartNumber=CRCW040220K0FKED, Power_W=63mW, Supplier Part Number 1=541-20.0KLCT-ND, TempCo="100 ppm/C", Tolerance_%=1%, Value2=0.063W, Value_Code=20k0, ValueDisplayed=20.0k
R9: library part CMP-0026367-2, "RES, 40.2 k, 1%, 0.063 W, AEC-Q200 Grade 0, 0402", Manufacturer=Vishay-Dale, Power_W=63mW, Supplier Part Number 1=541-40.2KLCT-ND, TempCo="100 ppm/C", Tolerance_%=1%, Value2=0.063W, Value_Code=40k2, ValueDisplayed=40.2k
R10: library part CMP-0026071-3, "RES, 1.00 k, 1%, 0.063 W, AEC-Q200 Grade 0, 0402", Manufacturer=Vishay-Dale, Power_W=63mW, Supplier Part Number 1=541-1.00KLCT-ND, TempCo="100 ppm/C", Tolerance_%=1%, Value2=0.063W, Value_Code=1k00, ValueDisplayed=1.00k
R11 R16 R17: library part CMP-0026753-1, "RES, 100 k, 1%, 0.063 W, AEC-Q200 Grade 0, 0402", Manufacturer="Stackpole Electronics Inc", Power_W=63mW, Supplier Part Number 1=RMCF0402FT100KCT-ND, TempCo="100 ppm/C", Tolerance_%=1%, Value2=0.063W, Value_Code=100k
R13 R14: library part CMP-0026071-3, "RES, 1.00 k, 1%, 0.063 W, AEC-Q200 Grade 0, 0402", Manufacturer=Vishay-Dale, PartNumber=CRCW04021K00FKED, Power_W=63mW, Supplier Part Number 1=541-1.00KLCT-ND, TempCo="100 ppm/C", Tolerance_%=1%, Value2=0.063W, Value_Code=1k00, ValueDisplayed=1.00k
R15: library part CMP-0025958-3, "RES, 10.0 k, 1%, 0.063 W, AEC-Q200 Grade 0, 0402", Manufacturer=Vishay-Dale, Power_W=63mW, Supplier Part Number 1=541-10.0KLCT-ND, TempCo="100 ppm/C", Tolerance_%=1%, Value2=0.063W, Value_Code=10k0, ValueDisplayed=10.0k
R18: library part CMP-0025958-3, "RES, 10.0 k, 1%, 0.063 W, AEC-Q200 Grade 0, 0402", Manufacturer=Vishay-Dale, PartNumber=CRCW040210K0FKED, Power_W=63mW, Supplier Part Number 1=541-10.0KLCT-ND, TempCo="100 ppm/C", Tolerance_%=1%, Value2=0.063W, Value_Code=10k0, ValueDisplayed=10.0k
R19: library part CMP-0086542-2, "RMCF/RMCP Series General Purpose Thick Film Standard Power and High Power Chip Resistor", Manufacturer=Stackpole, PartNumber=RMCF0402ZT0R00, TempCo=-
R20: library part CMP-0026622-3, "RES, 9.76 k, 1%, 0.063 W, AEC-Q200 Grade 0, 0402", Manufacturer=Vishay-Dale, PartNumber=CRCW04029K76FKED, Power_W=63mW, Supplier Part Number 1=541-9.76KLCT-ND, TempCo="100 ppm/C", Tolerance_%=1%, Value2=0.063W, Value_Code=9k76, ValueDisplayed=9.76k
TP1: library part CMP-0055147-2, "Test Point, Multipurpose, Red, TH", Color=Red, Manufacturer="Keystone Electronics", PartNumber=5010, Supplier Part Number 1=36-5010-ND
TP2 TP3 TP5 TP12: library part CMP-0055148-2, "Test Point, Multipurpose, Black, TH", Color=Black, Manufacturer="Keystone Electronics", PartNumber=5011, Supplier Part Number 1=36-5011-ND
TP4 TP7 TP8 TP9 TP10 TP11: library part CMP-0055149-2, "Test Point, Multipurpose, White, TH", Color=White, Manufacturer="Keystone Electronics", PartNumber=5012, Supplier Part Number 1=36-5012-ND
TP6: library part CMP-0055151-2, "Test Point, Multipurpose, Yellow, TH", Color=Yellow, Manufacturer="Keystone Electronics", PartNumber=5014, Supplier Part Number 1=36-5014-ND
U1: library part CMP-0860171-2, "LM61495QRPHRQ1, RPH0016A (VQFN-HR-16)", Alternate Manufacturer="Texas Instruments"

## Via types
v1: diameter 18, hole 8, Top Layer to Bottom Layer, tented both sides, 66 vias
v2: diameter 20, hole 10, Top Layer to Bottom Layer, tented both sides, 44 vias
v3: diameter 30, hole 20, Top Layer to Bottom Layer, 44 vias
